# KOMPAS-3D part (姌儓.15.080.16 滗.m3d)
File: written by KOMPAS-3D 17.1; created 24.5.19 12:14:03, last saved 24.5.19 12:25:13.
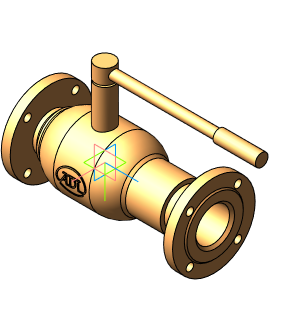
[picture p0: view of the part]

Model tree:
1. Операция без истории:1  (labels: Сталь 20  ГОСТ 1050-2013)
